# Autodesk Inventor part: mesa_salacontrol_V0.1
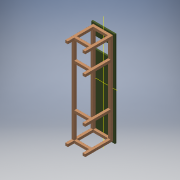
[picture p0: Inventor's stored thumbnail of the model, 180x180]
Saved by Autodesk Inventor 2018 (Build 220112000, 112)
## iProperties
Created: 2018-07
Part Number: mesa_salacontrol_V0.1
Material: Generic
Document SubType Name: Modeling
Designer: Gordillo
Density: 1 g/cm^3
Appearance: Default
Author: Gordillo
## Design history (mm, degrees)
sketch "Sketch1"
  geometry: L1 (525, 0)-(-525, 0) reference; L2 (0, -2100)-(0, 2100) reference; L3 (375, 1500)-(-375, 1500); L4 (-375, 1500)-(-375, -1500); L5 (-375, -1500)-(375, -1500); L6 (375, -1500)-(375, 1500); 1 further point
  constraints: 8 end point, 2 parallel, 1 horizontal, 1 perpendicular, 2 other
  dimensions: "profundidad_mesacontrol" = 750 distance of L5.end L4.end; "largo_mesacontrol" = 3000 distance of L4.end L3.end
extrude "Extrusion1" new body sketch "Sketch1" distance "d2" = 50; taper "d3" = 0 deg
fillet "Fillet1" dims "d4" = 12
sketch "Sketch2"
  geometry: L1 (315, 1450)-(235, 1450); L2 (235, 1450)-(235, -1450); L3 (235, -1450)-(315, -1450); L4 (315, -1450)-(315, 1450); L5 (-616, 0)-(616, 0) reference; L6 (375, 1500)-(375, -1500) reference; L7 (0, -2100)-(0, 2100) reference; L8 (-315, -1450)-(-315, 1450); L9 (-315, 1450)-(-235, 1450); L10 (-235, 1450)-(-235, -1450); L11 (-235, -1450)-(-315, -1450); L12 (315, 1450)-(-315, 1450); L13 (-315, 1450)-(-315, 1370); L14 (-315, 1370)-(315, 1370); L15 (315, 1370)-(315, 1450); L16 (-315, -1370)-(315, -1370); L17 (315, -1450)-(-315, -1450); L18 (-315, 1450)-(-315, -1450); L19 (315, 1450)-(315, -1450); L20 (235, -1450)-(235, 1450); L21 (-235, -1450)-(-235, 1450); L22 (315, -1450)-(-315, -1450); L23 (-315, -1450)-(-315, -1370); L24 (-315, -1370)-(315, -1370); L25 (315, -1370)-(315, -1450); 1 further point
  constraints: 44 end point, 15 symmetric about line, 6 parallel, 3 horizontal, 3 perpendicular, 2 point on line, 1 other
  dimensions: "ancho_liston" = 80 distance of L3.end L2.end; "d6" = 2900 distance of L2.end L1.end; "d7" = 60 distance between parallel lines of L6 L4; "d8" = 80 distance between parallel lines of L12 L14 (= ancho_liston)
extrude "Extrusion2" new body sketch "Sketch2" distance "d9" = 80 (= ancho_liston); taper "d10" = 0 deg
sketch "Sketch3"
  geometry: L1 (315, -1450)-(315, 1450) reference; L2 (315, 1450)-(-315, 1450) reference; L3 (-315, 1450)-(-315, -1450) reference; L4 (-315, -1450)-(315, -1450) reference; L5 (235, -1370)-(-235, -1370) reference; L6 (-235, -1370)-(-235, 1370) reference; L7 (-235, 1370)-(235, 1370) reference; L8 (235, 1370)-(235, -1370) reference; L9 (315, 1450)-(235, 1450); L10 (235, 1450)-(235, 1370); L11 (235, 1370)-(315, 1370); L12 (315, 1370)-(315, 1450); L13 (-235, -1370)-(-235, 1370) reference; L14 (-315, 1450)-(-235, 1450); L15 (-235, 1450)-(-235, 1370); L16 (-235, 1370)-(-315, 1370); L17 (-315, 1370)-(-315, 1450); L18 (-235, -1370)-(-315, -1370); L19 (-315, -1370)-(-315, -1450); L20 (-315, -1450)-(-235, -1450); L21 (-235, -1450)-(-235, -1370); L22 (235, 1370)-(235, -1370) reference; L23 (235, -1370)-(315, -1370); L24 (315, -1370)-(315, -1450); L25 (315, -1450)-(235, -1450); L26 (235, -1450)-(235, -1370); 1 further point
  constraints: 32 end point, 8 parallel, 4 horizontal, 4 perpendicular
extrude "Extrusion3" join sketch "Sketch3" taper "d12" = 0 deg; distance "largo_pata_mesacontrol" = 800
sketch "Sketch4"
  geometry: L1 (0, 0)-(0, -800) reference; L2 (80, 80)-(80, -800) reference; L3 (0, -520)-(80, -520); L4 (80, -520)-(80, -600); L5 (80, -600)-(0, -600); L6 (0, -600)-(0, -520); L7 (0, -800)-(80, -800) reference; 1 further point
  constraints: 8 end point, 2 parallel, 2 point on line, 1 horizontal, 1 perpendicular
  dimensions: "d13" = 80 distance of L3.end L4.end (= ancho_liston); "d14" = 200 distance between parallel lines of L7 L5
extrude "Extrusion4" join sketch "Sketch4" stored distance "d15" = 800; taper "d16" = 0 deg
sketch "Sketch5"
  geometry: L1 (80, 280)-(2820, 280) reference; L2 (0, 880)-(0, 0) reference; L3 (80, 200)-(2820, 200) reference; L4 (80, 280)-(0, 280); L5 (0, 280)-(0, 200); L6 (0, 200)-(80, 200); L7 (80, 200)-(80, 280); L8 (2900, 880)-(2900, 0) reference; L9 (2820, 280)-(2900, 280); L10 (2900, 280)-(2900, 200); L11 (2900, 200)-(2820, 200); L12 (2820, 200)-(2820, 280); 1 further point
  constraints: 16 end point, 4 parallel, 2 horizontal, 2 perpendicular, 2 point on line
  dimensions: "d17" = 80 distance between parallel lines of L6 L4 (= ancho_liston); "d18" = 80 distance between parallel lines of L9 L11 (= ancho_liston)
extrude "Extrusion5" join sketch "Sketch5" stored distance "d19" = 800; taper "d20" = 0 deg
sketch "Sketch6"
  geometry: L1 (315, -1450)-(315, 1450) reference; L2 (235, 1370)-(235, -1370) reference; L3 (315, 820)-(235, 820); L4 (235, 820)-(235, 740); L5 (235, 740)-(315, 740); L6 (315, 740)-(315, 820); L7 (235, 1370)-(315, 1370) reference; L8 (315, -540)-(235, -540); L9 (235, -540)-(235, -620); L10 (235, -620)-(315, -620); L11 (315, -620)-(315, -540); L12 (235, -1370)-(315, -1370) reference; 1 further point
  constraints: 16 end point, 4 parallel, 4 point on line, 2 horizontal, 2 perpendicular
  dimensions: "d21" = 80 distance between parallel lines of L3 L5 (= ancho_liston); "ancho_cajon_izq" = 550 distance between parallel lines of L7 L3; "d23" = 80 distance between parallel lines of L10 L8 (= ancho_liston); "ancho_cajon_der" = 750 distance between parallel lines of L12 L10
extrude "Extrusion6" join sketch "Sketch6" distance "d25" = 800 (= largo_pata_mesacontrol); taper "d26" = 0 deg
sketch "Sketch7"
  geometry: L1 (-2740, 0)-(0, 0) reference; L2 (-2740, 0)-(0, 0) reference; L3 (-2740, 80)-(0, 80) reference; L4 (-2740, 80)-(0, 80) reference; L5 (-2740, 80)-(0, 80) reference; L6 (-2740, 0)-(0, 0) reference; L7 (-2190, 80)-(-2110, 80); L8 (-2110, 80)-(-2110, 0); L9 (-2110, 0)-(-2190, 0); L10 (-2190, 0)-(-2190, 80); L11 (-2740, 600)-(-2740, 80) reference; L12 (-2740, 600)-(-2740, 80) reference; L13 (-2740, 0)-(-2740, -200) reference; L14 (-2740, 0)-(-2740, -200) reference; L15 (-830, 80)-(-750, 80); L16 (-750, 80)-(-750, 0); L17 (-750, 0)-(-830, 0); L18 (-830, 0)-(-830, 80); L19 (0, 600)-(0, 80) reference; L20 (0, 600)-(0, 80) reference; L21 (0, 0)-(0, -200) reference; L22 (0, 0)-(0, -200) reference; 1 further point
  constraints: 16 end point, 4 parallel, 4 point on line, 2 horizontal, 2 perpendicular
  dimensions: "d27" = 80 distance between parallel lines of L10 L8 (= ancho_liston); "d28" = 550 distance between parallel lines of L11 L10 (= ancho_cajon_izq); "d29" = 80 distance between parallel lines of L18 L16 (= ancho_liston); "d30" = 750 distance between parallel lines of L19 L16 (= ancho_cajon_der)
extrude "Extrusion7" join sketch "Sketch7" stored distance "d31" = 800 (= largo_pata_mesacontrol); taper "d32" = 0 deg
sketch "Sketch8"
  geometry: L1 (-310.496, -1153.27)-(221.783, -1153.27); L2 (221.783, -1153.27)-(221.783, -787.981); L3 (221.783, -787.981)-(-310.496, -787.981); L4 (-310.496, -787.981)-(-310.496, -1153.27); 1 further point
  constraints: 8 end point, 2 parallel, 1 horizontal, 1 perpendicular
extrude "Extrusion8" cut sketch "Sketch8" stored distance "d33" = 10; taper "d34" = 0 deg
node "tabla_mesacontrol"
node "armazon_mesacontrol"
node "Projected Loop1"
node "Projected Loop2"
node "Projected Loop3"
node "Projected Loop4"
node "Projected Loop5"
node "Projected Loop6"
node "Projected Loop7"
